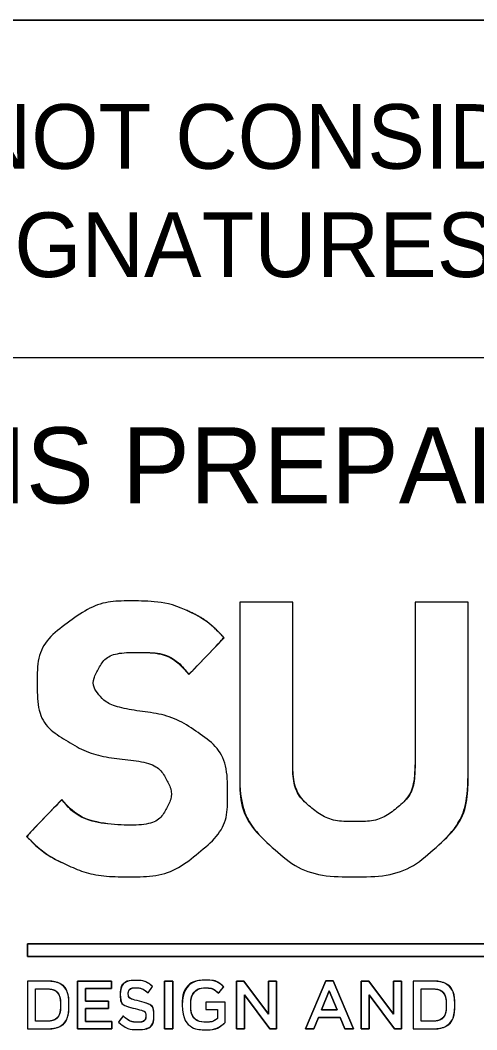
# Model space of a CAD drawing. Extents: x 1184048.9 to 1184122, y 1246638.9 to 1246660.6.
# Drawn here: x 1184113.44 to 1184113.868, y 1246655.061 to 1246656.008 of the extents above; entities that cross this region are included whole.
import ezdxf

# ---------------------------------------------------------------- set-up
doc = ezdxf.new("R2010")
doc.units = 0
for name, color, linetype in [('Sheet Plan CELL', 7, 'Continuous'), ('Sheet Sticker Exception Certification CELL', 7, 'Continuous'), ('Sheet Title CELL', 7, 'Continuous')]:
    doc.layers.add(name, color=color, linetype=linetype)

msp = doc.modelspace()

# ---------------------------------------------------------------- linework, layer by layer
at = {"layer": 'Sheet Plan CELL'}
for p, q in [((1184114.76652, 1246656.00828), (1184112.78593, 1246656.00828)), ((1184113.59833, 1246655.39448), (1184113.63142, 1246655.42897)), ((1184113.47921, 1246655.27717), (1184113.44612, 1246655.24266)), ((1184113.56025, 1246655.09595), (1184113.56432, 1246655.10192)), ((1184113.62619, 1246655.09563), (1184113.631, 1246655.1016)), ((1184113.53393, 1246655.09453), (1184113.53393, 1246655.0944)), ((1184113.54151, 1246655.09511), (1184113.54151, 1246655.09524)), ((1184113.47792, 1246655.08444), (1184113.47792, 1246655.08432)), ((1184113.48587, 1246655.08444), (1184113.48587, 1246655.08457)), ((1184113.59217, 1246655.08444), (1184113.59217, 1246655.08432)), ((1184113.60011, 1246655.08444), (1184113.60011, 1246655.08457)), ((1184113.83986, 1246655.08444), (1184113.83986, 1246655.08432)), ((1184113.84781, 1246655.08444), (1184113.84781, 1246655.08457)), ((1184113.53676, 1246655.07416), (1184113.5322, 1246655.0685)), ((1184113.55803, 1246655.0741), (1184113.55803, 1246655.07397)), ((1184113.56561, 1246655.07474), (1184113.56561, 1246655.07487))]:
    msp.add_line(p, q, dxfattribs=at)
for points in [[(1184113.69574, 1246655.31341), (1184113.69574, 1246655.46244), (1184113.64601, 1246655.46244), (1184113.64601, 1246655.2996)], [(1184113.86024, 1246655.2996), (1184113.86024, 1246655.46244), (1184113.81051, 1246655.46244), (1184113.81051, 1246655.31341)], [(1184114.65214, 1246655.12988), (1184113.44708, 1246655.12988), (1184113.44708, 1246655.14185), (1184114.65214, 1246655.14185), (1184114.65214, 1246655.12988)], [(1184114.65214, 1246655.14185), (1184113.44708, 1246655.14185), (1184113.44708, 1246655.12988), (1184114.65214, 1246655.12988), (1184114.65214, 1246655.14185)], [(1184113.46294, 1246655.10694), (1184113.44685, 1246655.10694), (1184113.44685, 1246655.06195), (1184113.46294, 1246655.06195)], [(1184113.46294, 1246655.06915), (1184113.45443, 1246655.06915), (1184113.45443, 1246655.09974), (1184113.46294, 1246655.09974)], [(1184113.49381, 1246655.10694), (1184113.5258, 1246655.10694), (1184113.5258, 1246655.09987), (1184113.50139, 1246655.09987), (1184113.50139, 1246655.08817), (1184113.52303, 1246655.08817), (1184113.52303, 1246655.0811), (1184113.50139, 1246655.0811), (1184113.50139, 1246655.06902), (1184113.5261, 1246655.06902), (1184113.5261, 1246655.06195), (1184113.49381, 1246655.06195), (1184113.49381, 1246655.10694)], [(1184113.49381, 1246655.06195), (1184113.5261, 1246655.06195), (1184113.5261, 1246655.06902), (1184113.50139, 1246655.06902), (1184113.50139, 1246655.0811), (1184113.52303, 1246655.0811), (1184113.52303, 1246655.08817), (1184113.50139, 1246655.08817), (1184113.50139, 1246655.09987), (1184113.5258, 1246655.09987), (1184113.5258, 1246655.10694), (1184113.49381, 1246655.10694), (1184113.49381, 1246655.06195)], [(1184113.57559, 1246655.10694), (1184113.58317, 1246655.10694), (1184113.58317, 1246655.06195), (1184113.57559, 1246655.06195), (1184113.57559, 1246655.10694)], [(1184113.57559, 1246655.06195), (1184113.58317, 1246655.06195), (1184113.58317, 1246655.10694), (1184113.57559, 1246655.10694), (1184113.57559, 1246655.06195)], [(1184113.64301, 1246655.10694), (1184113.65003, 1246655.10694), (1184113.67315, 1246655.07583), (1184113.67315, 1246655.10694), (1184113.68061, 1246655.10694), (1184113.68061, 1246655.06195), (1184113.67426, 1246655.06195), (1184113.65047, 1246655.09396), (1184113.65047, 1246655.06195), (1184113.64301, 1246655.06195), (1184113.64301, 1246655.10694)], [(1184113.64301, 1246655.06195), (1184113.65047, 1246655.06195), (1184113.65047, 1246655.09396), (1184113.67426, 1246655.06195), (1184113.68061, 1246655.06195), (1184113.68061, 1246655.10694), (1184113.67315, 1246655.10694), (1184113.67315, 1246655.07583), (1184113.65003, 1246655.10694), (1184113.64301, 1246655.10694), (1184113.64301, 1246655.06195)], [(1184113.7267, 1246655.10726), (1184113.73373, 1246655.10726), (1184113.75272, 1246655.06195), (1184113.7447, 1246655.06195), (1184113.74032, 1246655.07281), (1184113.71992, 1246655.07281), (1184113.71548, 1246655.06195), (1184113.70772, 1246655.06195), (1184113.7267, 1246655.10726)], [(1184113.70772, 1246655.06195), (1184113.71548, 1246655.06195), (1184113.71992, 1246655.07281), (1184113.74032, 1246655.07281), (1184113.7447, 1246655.06195), (1184113.75272, 1246655.06195), (1184113.73373, 1246655.10726), (1184113.7267, 1246655.10726), (1184113.70772, 1246655.06195)], [(1184113.7601, 1246655.10694), (1184113.76713, 1246655.10694), (1184113.79024, 1246655.07583), (1184113.79024, 1246655.10694), (1184113.79771, 1246655.10694), (1184113.79771, 1246655.06195), (1184113.79136, 1246655.06195), (1184113.76756, 1246655.09396), (1184113.76756, 1246655.06195), (1184113.7601, 1246655.06195), (1184113.7601, 1246655.10694)], [(1184113.7601, 1246655.06195), (1184113.76756, 1246655.06195), (1184113.76756, 1246655.09396), (1184113.79136, 1246655.06195), (1184113.79771, 1246655.06195), (1184113.79771, 1246655.10694), (1184113.79024, 1246655.10694), (1184113.79024, 1246655.07583), (1184113.76713, 1246655.10694), (1184113.7601, 1246655.10694), (1184113.7601, 1246655.06195)], [(1184113.82488, 1246655.10694), (1184113.80879, 1246655.10694), (1184113.80879, 1246655.06195), (1184113.82488, 1246655.06195)], [(1184113.82488, 1246655.06915), (1184113.81638, 1246655.06915), (1184113.81638, 1246655.09974), (1184113.82488, 1246655.09974)], [(1184113.73755, 1246655.07982), (1184113.7301, 1246655.09781), (1184113.7227, 1246655.07982), (1184113.73755, 1246655.07982)], [(1184113.7227, 1246655.07982), (1184113.7301, 1246655.09781), (1184113.73755, 1246655.07982), (1184113.7227, 1246655.07982)], [(1184113.63254, 1246655.06818), (1184113.63254, 1246655.08708), (1184113.61417, 1246655.08708), (1184113.61417, 1246655.0802), (1184113.62521, 1246655.0802), (1184113.62521, 1246655.07178)]]:
    msp.add_lwpolyline(points, dxfattribs=at)
for points, degree in [([(1184113.59584, 1246655.45484), (1184113.60854, 1246655.44911), (1184113.6204, 1246655.44048), (1184113.63142, 1246655.42897), (1184113.63142, 1246655.42897), (1184113.59833, 1246655.39448), (1184113.59833, 1246655.39448), (1184113.5873, 1246655.40828), (1184113.57187, 1246655.41518), (1184113.552, 1246655.41518), (1184113.53215, 1246655.41518), (1184113.51946, 1246655.41029), (1184113.51395, 1246655.4005), (1184113.50844, 1246655.39074), (1184113.50844, 1246655.38241), (1184113.51395, 1246655.37551), (1184113.51946, 1246655.3686), (1184113.53215, 1246655.36342), (1184113.552, 1246655.35998), (1184113.57295, 1246655.35769), (1184113.592, 1246655.35049), (1184113.60909, 1246655.33841), (1184113.62618, 1246655.32634), (1184113.63472, 1246655.30708), (1184113.63472, 1246655.28062), (1184113.63472, 1246655.25991), (1184113.62561, 1246655.2421), (1184113.60735, 1246655.22715), (1184113.5891, 1246655.2122), (1184113.56783, 1246655.20472), (1184113.54355, 1246655.20472), (1184113.52051, 1246655.20472), (1184113.50126, 1246655.20817), (1184113.48581, 1246655.21507), (1184113.47037, 1246655.22198), (1184113.45714, 1246655.23118), (1184113.44612, 1246655.24266), (1184113.44612, 1246655.24266), (1184113.47921, 1246655.27717), (1184113.47921, 1246655.27717), (1184113.49024, 1246655.26337), (1184113.50899, 1246655.25532), (1184113.53546, 1246655.25302), (1184113.55753, 1246655.25302), (1184113.57129, 1246655.25792), (1184113.57675, 1246655.26769), (1184113.5822, 1246655.27746), (1184113.5822, 1246655.28723), (1184113.57675, 1246655.29701), (1184113.57129, 1246655.30679), (1184113.55753, 1246655.31281), (1184113.53546, 1246655.31512), (1184113.51561, 1246655.31742), (1184113.49741, 1246655.32375), (1184113.48086, 1246655.3341), (1184113.46432, 1246655.34446), (1184113.45603, 1246655.36227), (1184113.45603, 1246655.38757), (1184113.45603, 1246655.41046), (1184113.46544, 1246655.42882), (1184113.48425, 1246655.44269), (1184113.50305, 1246655.45656), (1184113.52238, 1246655.46348), (1184113.54224, 1246655.46348), (1184113.56529, 1246655.46348), (1184113.58316, 1246655.46062), (1184113.59584, 1246655.45484)], 3), ([(1184113.59584, 1246655.45484), (1184113.58316, 1246655.46062), (1184113.56529, 1246655.46348), (1184113.54224, 1246655.46348), (1184113.52238, 1246655.46348), (1184113.50305, 1246655.45656), (1184113.48425, 1246655.44269), (1184113.46544, 1246655.42882), (1184113.45603, 1246655.41046), (1184113.45603, 1246655.38757), (1184113.45603, 1246655.36227), (1184113.46432, 1246655.34446), (1184113.48086, 1246655.3341), (1184113.49741, 1246655.32375), (1184113.51561, 1246655.31742), (1184113.53546, 1246655.31512), (1184113.55753, 1246655.31281), (1184113.57129, 1246655.30679), (1184113.57675, 1246655.29701), (1184113.5822, 1246655.28723), (1184113.5822, 1246655.27746), (1184113.57675, 1246655.26769), (1184113.57129, 1246655.25792), (1184113.55753, 1246655.25302), (1184113.53546, 1246655.25302), (1184113.50899, 1246655.25532), (1184113.49024, 1246655.26337), (1184113.47921, 1246655.27717)], 3), ([(1184113.69574, 1246655.46244), (1184113.69574, 1246655.46244), (1184113.69574, 1246655.31341), (1184113.69574, 1246655.31341), (1184113.69574, 1246655.29384), (1184113.70137, 1246655.27948), (1184113.7124, 1246655.27027), (1184113.72345, 1246655.26107), (1184113.73729, 1246655.25647), (1184113.75384, 1246655.25647), (1184113.77038, 1246655.25647), (1184113.78355, 1246655.26107), (1184113.79459, 1246655.27027), (1184113.80561, 1246655.27948), (1184113.81051, 1246655.29384), (1184113.81051, 1246655.31341), (1184113.81051, 1246655.31341), (1184113.81051, 1246655.46244), (1184113.81051, 1246655.46244), (1184113.81051, 1246655.46244), (1184113.86024, 1246655.46244), (1184113.86024, 1246655.46244), (1184113.86024, 1246655.46244), (1184113.86024, 1246655.2996), (1184113.86024, 1246655.2996), (1184113.86024, 1246655.27314), (1184113.85064, 1246655.25073), (1184113.83023, 1246655.23233), (1184113.80982, 1246655.21393), (1184113.78449, 1246655.20472), (1184113.7536, 1246655.20472), (1184113.72271, 1246655.20472), (1184113.69703, 1246655.21393), (1184113.67664, 1246655.23233), (1184113.65622, 1246655.25073), (1184113.64601, 1246655.27314), (1184113.64601, 1246655.2996), (1184113.64601, 1246655.2996), (1184113.64601, 1246655.46244), (1184113.64601, 1246655.46244), (1184113.64601, 1246655.46244), (1184113.69574, 1246655.46244), (1184113.69574, 1246655.46244)], 3), ([(1184113.63142, 1246655.42897), (1184113.6204, 1246655.44048), (1184113.60854, 1246655.44911), (1184113.59584, 1246655.45484)], 2), ([(1184113.44612, 1246655.24266), (1184113.45714, 1246655.23118), (1184113.47037, 1246655.22198), (1184113.48581, 1246655.21507), (1184113.50126, 1246655.20817), (1184113.52051, 1246655.20472), (1184113.54355, 1246655.20472), (1184113.56783, 1246655.20472), (1184113.5891, 1246655.2122), (1184113.60735, 1246655.22715), (1184113.62561, 1246655.2421), (1184113.63472, 1246655.25991), (1184113.63472, 1246655.28062), (1184113.63472, 1246655.30708), (1184113.62618, 1246655.32634), (1184113.60909, 1246655.33841), (1184113.592, 1246655.35049), (1184113.57295, 1246655.35769), (1184113.552, 1246655.35998), (1184113.53215, 1246655.36342), (1184113.51946, 1246655.3686), (1184113.51395, 1246655.37551), (1184113.50844, 1246655.38241), (1184113.50844, 1246655.39074), (1184113.51395, 1246655.4005), (1184113.51946, 1246655.41029), (1184113.53215, 1246655.41518), (1184113.552, 1246655.41518), (1184113.57187, 1246655.41518), (1184113.5873, 1246655.40828), (1184113.59833, 1246655.39448)], 3), ([(1184113.81051, 1246655.31341), (1184113.81051, 1246655.29384), (1184113.80561, 1246655.27948), (1184113.79459, 1246655.27027), (1184113.78355, 1246655.26107), (1184113.77038, 1246655.25647), (1184113.75384, 1246655.25647), (1184113.73729, 1246655.25647), (1184113.72345, 1246655.26107), (1184113.7124, 1246655.27027), (1184113.70137, 1246655.27948), (1184113.69574, 1246655.29384), (1184113.69574, 1246655.31341)], 3), ([(1184113.64601, 1246655.2996), (1184113.64601, 1246655.27314), (1184113.65622, 1246655.25073), (1184113.67664, 1246655.23233), (1184113.69703, 1246655.21393), (1184113.72271, 1246655.20472), (1184113.7536, 1246655.20472), (1184113.78449, 1246655.20472), (1184113.80982, 1246655.21393), (1184113.83023, 1246655.23233), (1184113.85064, 1246655.25073), (1184113.86024, 1246655.27314), (1184113.86024, 1246655.2996)], 3), ([(1184113.44685, 1246655.10694), (1184113.44685, 1246655.10694), (1184113.46294, 1246655.10694), (1184113.46294, 1246655.10694), (1184113.4765, 1246655.10694), (1184113.48587, 1246655.09723), (1184113.48587, 1246655.08457), (1184113.48587, 1246655.08457), (1184113.48587, 1246655.08444), (1184113.48587, 1246655.08444), (1184113.48587, 1246655.07178), (1184113.4765, 1246655.06195), (1184113.46294, 1246655.06195), (1184113.46294, 1246655.06195), (1184113.44685, 1246655.06195), (1184113.44685, 1246655.06195), (1184113.44685, 1246655.06195), (1184113.44685, 1246655.10694), (1184113.44685, 1246655.10694)], 3), ([(1184113.45443, 1246655.09974), (1184113.45443, 1246655.09974), (1184113.45443, 1246655.06915), (1184113.45443, 1246655.06915), (1184113.45443, 1246655.06915), (1184113.46294, 1246655.06915), (1184113.46294, 1246655.06915), (1184113.472, 1246655.06915), (1184113.47792, 1246655.07551), (1184113.47792, 1246655.08432), (1184113.47792, 1246655.08432), (1184113.47792, 1246655.08444), (1184113.47792, 1246655.08444), (1184113.47792, 1246655.09325), (1184113.472, 1246655.09974), (1184113.46294, 1246655.09974), (1184113.46294, 1246655.09974), (1184113.45443, 1246655.09974), (1184113.45443, 1246655.09974)], 3), ([(1184113.48587, 1246655.08457), (1184113.48587, 1246655.09723), (1184113.4765, 1246655.10694), (1184113.46294, 1246655.10694)], 2), ([(1184113.46294, 1246655.09974), (1184113.472, 1246655.09974), (1184113.47792, 1246655.09325), (1184113.47792, 1246655.08444)], 2), ([(1184113.5322, 1246655.0685), (1184113.5322, 1246655.0685), (1184113.53676, 1246655.07416), (1184113.53676, 1246655.07416), (1184113.54089, 1246655.07043), (1184113.54508, 1246655.06831), (1184113.55039, 1246655.06831), (1184113.55507, 1246655.06831), (1184113.55803, 1246655.07063), (1184113.55803, 1246655.07397), (1184113.55803, 1246655.07397), (1184113.55803, 1246655.0741), (1184113.55803, 1246655.0741), (1184113.55803, 1246655.07731), (1184113.5563, 1246655.07904), (1184113.54829, 1246655.08097), (1184113.53911, 1246655.08329), (1184113.53393, 1246655.08611), (1184113.53393, 1246655.0944), (1184113.53393, 1246655.0944), (1184113.53393, 1246655.09453), (1184113.53393, 1246655.09453), (1184113.53393, 1246655.10225), (1184113.54009, 1246655.10758), (1184113.54866, 1246655.10758), (1184113.55495, 1246655.10758), (1184113.55994, 1246655.10559), (1184113.56432, 1246655.10192), (1184113.56432, 1246655.10192), (1184113.56025, 1246655.09595), (1184113.56025, 1246655.09595), (1184113.55637, 1246655.09897), (1184113.55249, 1246655.10057), (1184113.54854, 1246655.10057), (1184113.5441, 1246655.10057), (1184113.54151, 1246655.0982), (1184113.54151, 1246655.09524), (1184113.54151, 1246655.09524), (1184113.54151, 1246655.09511), (1184113.54151, 1246655.09511), (1184113.54151, 1246655.09164), (1184113.54348, 1246655.0901), (1184113.5518, 1246655.08804), (1184113.56092, 1246655.08573), (1184113.56561, 1246655.08232), (1184113.56561, 1246655.07487), (1184113.56561, 1246655.07487), (1184113.56561, 1246655.07474), (1184113.56561, 1246655.07474), (1184113.56561, 1246655.06632), (1184113.55926, 1246655.06131), (1184113.5502, 1246655.06131), (1184113.5436, 1246655.06131), (1184113.53738, 1246655.06368), (1184113.5322, 1246655.0685)], 3), ([(1184113.56432, 1246655.10192), (1184113.55994, 1246655.10559), (1184113.55495, 1246655.10758), (1184113.54866, 1246655.10758), (1184113.54009, 1246655.10758), (1184113.53393, 1246655.10225), (1184113.53393, 1246655.09453)], 3), ([(1184113.54151, 1246655.09524), (1184113.54151, 1246655.0982), (1184113.5441, 1246655.10057), (1184113.54854, 1246655.10057), (1184113.55249, 1246655.10057), (1184113.55637, 1246655.09897), (1184113.56025, 1246655.09595)], 3), ([(1184113.59217, 1246655.08432), (1184113.59217, 1246655.08432), (1184113.59217, 1246655.08444), (1184113.59217, 1246655.08444), (1184113.59217, 1246655.09704), (1184113.60141, 1246655.10771), (1184113.61441, 1246655.10771), (1184113.62194, 1246655.10771), (1184113.62656, 1246655.10552), (1184113.631, 1246655.1016), (1184113.631, 1246655.1016), (1184113.62619, 1246655.09563), (1184113.62619, 1246655.09563), (1184113.62286, 1246655.09858), (1184113.6196, 1246655.10045), (1184113.61411, 1246655.10045), (1184113.60616, 1246655.10045), (1184113.60011, 1246655.09318), (1184113.60011, 1246655.08457), (1184113.60011, 1246655.08457), (1184113.60011, 1246655.08444), (1184113.60011, 1246655.08444), (1184113.60011, 1246655.07519), (1184113.60598, 1246655.06838), (1184113.61479, 1246655.06838), (1184113.61885, 1246655.06838), (1184113.62255, 1246655.06973), (1184113.62521, 1246655.07178), (1184113.62521, 1246655.07178), (1184113.62521, 1246655.0802), (1184113.62521, 1246655.0802), (1184113.62521, 1246655.0802), (1184113.61417, 1246655.0802), (1184113.61417, 1246655.0802), (1184113.61417, 1246655.0802), (1184113.61417, 1246655.08708), (1184113.61417, 1246655.08708), (1184113.61417, 1246655.08708), (1184113.63254, 1246655.08708), (1184113.63254, 1246655.08708), (1184113.63254, 1246655.08708), (1184113.63254, 1246655.06818), (1184113.63254, 1246655.06818), (1184113.62829, 1246655.06439), (1184113.62218, 1246655.06118), (1184113.61454, 1246655.06118), (1184113.60104, 1246655.06118), (1184113.59217, 1246655.0712), (1184113.59217, 1246655.08432)], 3), ([(1184113.631, 1246655.1016), (1184113.62656, 1246655.10552), (1184113.62194, 1246655.10771), (1184113.61441, 1246655.10771), (1184113.60141, 1246655.10771), (1184113.59217, 1246655.09704), (1184113.59217, 1246655.08444)], 3), ([(1184113.60011, 1246655.08457), (1184113.60011, 1246655.09318), (1184113.60616, 1246655.10045), (1184113.61411, 1246655.10045), (1184113.6196, 1246655.10045), (1184113.62286, 1246655.09858), (1184113.62619, 1246655.09563)], 3), ([(1184113.80879, 1246655.10694), (1184113.80879, 1246655.10694), (1184113.82488, 1246655.10694), (1184113.82488, 1246655.10694), (1184113.83844, 1246655.10694), (1184113.84781, 1246655.09723), (1184113.84781, 1246655.08457), (1184113.84781, 1246655.08457), (1184113.84781, 1246655.08444), (1184113.84781, 1246655.08444), (1184113.84781, 1246655.07178), (1184113.83844, 1246655.06195), (1184113.82488, 1246655.06195), (1184113.82488, 1246655.06195), (1184113.80879, 1246655.06195), (1184113.80879, 1246655.06195), (1184113.80879, 1246655.06195), (1184113.80879, 1246655.10694), (1184113.80879, 1246655.10694)], 3), ([(1184113.81638, 1246655.09974), (1184113.81638, 1246655.09974), (1184113.81638, 1246655.06915), (1184113.81638, 1246655.06915), (1184113.81638, 1246655.06915), (1184113.82488, 1246655.06915), (1184113.82488, 1246655.06915), (1184113.83394, 1246655.06915), (1184113.83986, 1246655.07551), (1184113.83986, 1246655.08432), (1184113.83986, 1246655.08432), (1184113.83986, 1246655.08444), (1184113.83986, 1246655.08444), (1184113.83986, 1246655.09325), (1184113.83394, 1246655.09974), (1184113.82488, 1246655.09974), (1184113.82488, 1246655.09974), (1184113.81638, 1246655.09974), (1184113.81638, 1246655.09974)], 3), ([(1184113.84781, 1246655.08457), (1184113.84781, 1246655.09723), (1184113.83844, 1246655.10694), (1184113.82488, 1246655.10694)], 2), ([(1184113.82488, 1246655.09974), (1184113.83394, 1246655.09974), (1184113.83986, 1246655.09325), (1184113.83986, 1246655.08444)], 2), ([(1184113.53393, 1246655.0944), (1184113.53393, 1246655.08611), (1184113.53911, 1246655.08329), (1184113.54829, 1246655.08097), (1184113.5563, 1246655.07904), (1184113.55803, 1246655.07731), (1184113.55803, 1246655.0741)], 3), ([(1184113.56561, 1246655.07487), (1184113.56561, 1246655.08232), (1184113.56092, 1246655.08573), (1184113.5518, 1246655.08804), (1184113.54348, 1246655.0901), (1184113.54151, 1246655.09164), (1184113.54151, 1246655.09511)], 3), ([(1184113.46294, 1246655.06195), (1184113.4765, 1246655.06195), (1184113.48587, 1246655.07178), (1184113.48587, 1246655.08444)], 2), ([(1184113.47792, 1246655.08432), (1184113.47792, 1246655.07551), (1184113.472, 1246655.06915), (1184113.46294, 1246655.06915)], 2), ([(1184113.59217, 1246655.08432), (1184113.59217, 1246655.0712), (1184113.60104, 1246655.06118), (1184113.61454, 1246655.06118), (1184113.62218, 1246655.06118), (1184113.62829, 1246655.06439), (1184113.63254, 1246655.06818)], 3), ([(1184113.62521, 1246655.07178), (1184113.62255, 1246655.06973), (1184113.61885, 1246655.06838), (1184113.61479, 1246655.06838), (1184113.60598, 1246655.06838), (1184113.60011, 1246655.07519), (1184113.60011, 1246655.08444)], 3), ([(1184113.82488, 1246655.06195), (1184113.83844, 1246655.06195), (1184113.84781, 1246655.07178), (1184113.84781, 1246655.08444)], 2), ([(1184113.83986, 1246655.08432), (1184113.83986, 1246655.07551), (1184113.83394, 1246655.06915), (1184113.82488, 1246655.06915)], 2), ([(1184113.5322, 1246655.0685), (1184113.53738, 1246655.06368), (1184113.5436, 1246655.06131), (1184113.5502, 1246655.06131), (1184113.55926, 1246655.06131), (1184113.56561, 1246655.06632), (1184113.56561, 1246655.07474)], 3), ([(1184113.55803, 1246655.07397), (1184113.55803, 1246655.07063), (1184113.55507, 1246655.06831), (1184113.55039, 1246655.06831), (1184113.54508, 1246655.06831), (1184113.54089, 1246655.07043), (1184113.53676, 1246655.07416)], 3)]:
    msp.add_open_spline(points, degree=degree, dxfattribs=at)
at = {"layer": 'Sheet Sticker Exception Certification CELL'}
for p, q in [((1184112.78589, 1246656.00828), (1184114.76646, 1246656.00828)), ((1184114.76646, 1246655.69165), (1184112.78589, 1246655.69165))]:
    msp.add_line(p, q, dxfattribs=at)
at = {"layer": 'Sheet Title CELL'}
for p, q in [((1184112.78589, 1246656.00828), (1184114.76646, 1246656.00828)), ((1184114.76646, 1246655.69165), (1184112.78589, 1246655.69165))]:
    msp.add_line(p, q, dxfattribs=at)

# ---------------------------------------------------------------- texts
at = {"layer": 'Sheet Plan CELL'}
msp.add_text('PLANS PREPARED BY:', height=0.071302, rotation=0, dxfattribs=at).set_placement((1184113.19648, 1246655.55507))
at = {"layer": 'Sheet Sticker Exception Certification CELL'}
for s, p in [('DOCUMENT NOT CONSIDERED FINAL', (1184112.90099, 1246655.86889)), ('UNLESS ALL SIGNATURES COMPLETED', (1184112.84424, 1246655.76729))]:
    msp.add_text(s, height=0.0606299, rotation=360, dxfattribs=at).set_placement(p)
at = {"layer": 'Sheet Title CELL'}
for s, p in [('DOCUMENT NOT CONSIDERED FINAL', (1184112.90099, 1246655.86889)), ('UNLESS ALL SIGNATURES COMPLETED', (1184112.84424, 1246655.76729))]:
    msp.add_text(s, height=0.0606299, rotation=360, dxfattribs=at).set_placement(p)

doc.saveas('drawing.dxf')
